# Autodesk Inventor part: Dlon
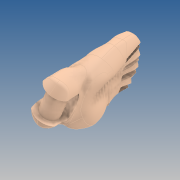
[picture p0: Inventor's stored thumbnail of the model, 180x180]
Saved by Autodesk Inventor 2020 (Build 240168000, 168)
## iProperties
Created: 2019-10
Part Number: Dlon
Material: GFRP
Document SubType Name: Modeling
Designer: yello
Density: 1.75 g/cm^3
Appearance: Default
Author: yello
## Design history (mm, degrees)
node "Palm"
workplane "Work Plane1"
workplane "Work Plane2"
sketch "Sketch13"
  geometry: L1 (0, 1.5)-(0, -1.5); A1 r 1.5 centre (0, 0) between (0, 1.5) and (0, -1.5)
  constraints: 2 end point, 2 point on circle, 1 centre point, 1 vertical
  dimensions: "d18" = 3 diameter of A1
sketch "Sketch14"
  geometry: L1 (0, -1.5)-(0, 1.5); A1 r 1.5 centre (0, 0) between (0, -1.5) and (0, 1.5); 1 further point
  constraints: 2 end point, 2 point on circle, 1 centre point, 1 vertical
  dimensions: "d19" = 3 diameter of A1
revolve "Revolution1" sketch "Sketch14" stored, may be unused: angle "d20" = 90 deg
revolve "Revolution2" stored, may be unused: angle "d21" = 90 deg
body "Solid1"
other parameters: "d16" = 0.5, "d17" = 0.5
